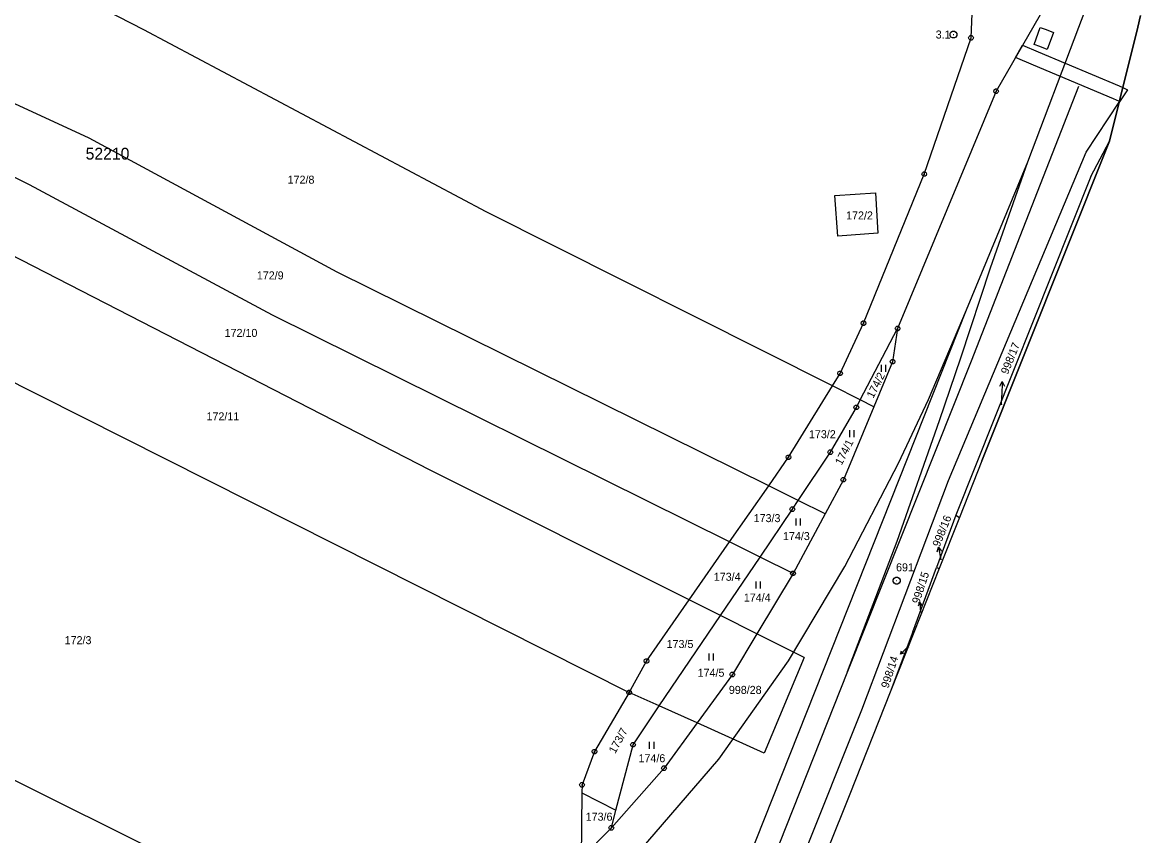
# Model space of a CAD drawing. Extents: x -755359 to -754474, y -1162585 to -1161655.
# Drawn here: x -754987.3 to -754749.7, y -1162144.3 to -1161971.6 of the extents above; entities that cross this region are included whole.
import ezdxf

# ---------------------------------------------------------------- set-up
doc = ezdxf.new("R2010")
doc.units = 0
for name, color, linetype in [('Vrstva 1', 7, 'Continuous'), ('Vrstva 11', 7, 'Continuous'), ('Vrstva 13', 7, 'Continuous'), ('Vrstva 2', 7, 'Continuous'), ('Vrstva 3', 7, 'Continuous'), ('Vrstva 4', 7, 'Continuous'), ('Vrstva 6', 7, 'Continuous'), ('Vrstva 7', 7, 'Continuous'), ('Vrstva 8', 7, 'Continuous')]:
    doc.layers.add(name, color=color, linetype=linetype)

msp = doc.modelspace()

# ---------------------------------------------------------------- linework, layer by layer
at = {"layer": 'Vrstva 1'}
for p, q in [((-754785.77, -1161974.89), (-754784.8, -1161953.94)), ((-754961.49, -1161973.19), (-754992.75, -1161957.04)), ((-754764.95, -1161959.34), (-754780.44, -1161986.21)), ((-754750.32, -1161972.64), (-754749.74, -1161970.12)), ((-754888.73, -1162011.84), (-754961.49, -1161973.19)), ((-754754.27, -1161988.55), (-754750.32, -1161972.64)), ((-754973.07, -1161996.16), (-755018.7, -1161975.2)), ((-754795.69, -1162003.82), (-754785.77, -1161974.89)), ((-754985.77, -1162006.08), (-755029.84, -1161984.47)), ((-754780.44, -1161986.21), (-754801.36, -1162036.63)), ((-754761.32, -1161999.17), (-754754.27, -1161988.55)), ((-754756.33, -1161996.85), (-754754.27, -1161988.55)), ((-754920.4, -1162024.65), (-754973.07, -1161996.16)), ((-754783.47, -1162064.75), (-754756.33, -1161996.85)), ((-754760.29, -1162004.33), (-754756.33, -1161996.85)), ((-754790.52, -1162068.93), (-754761.32, -1161999.17)), ((-754808.6, -1162035.49), (-754795.69, -1162003.82)), ((-754760.29, -1162004.33), (-754789, -1162076.26)), ((-754934.11, -1162033.82), (-754985.77, -1162006.08)), ((-754814.69, -1162008.38), (-754806.06, -1162007.78)), ((-754814.09, -1162016.99), (-754814.69, -1162008.38)), ((-754806.06, -1162007.78), (-754805.56, -1162016.36)), ((-754815.21, -1162048.8), (-754888.73, -1162011.84)), ((-754805.56, -1162016.36), (-754814.09, -1162016.99)), ((-754900.68, -1162066.68), (-754997.44, -1162017.02)), ((-755045.32, -1162019.78), (-754858.37, -1162113.93)), ((-754828.75, -1162070.02), (-754920.4, -1162024.65)), ((-754837.06, -1162081.94), (-754934.11, -1162033.82)), ((-754813.58, -1162046.15), (-754808.6, -1162035.49)), ((-754809.29, -1162051.78), (-754801.36, -1162036.63)), ((-754801.36, -1162036.63), (-754802.42, -1162043.68)), ((-754802.42, -1162043.68), (-754806.4, -1162053.23)), ((-754815.21, -1162048.8), (-754813.58, -1162046.15)), ((-754824.54, -1162063.98), (-754815.21, -1162048.8)), ((-754809.29, -1162051.78), (-754815.21, -1162048.8)), ((-754810.12, -1162053.37), (-754809.29, -1162051.78)), ((-754806.4, -1162053.23), (-754809.29, -1162051.78)), ((-754815.64, -1162062.89), (-754810.12, -1162053.37)), ((-754806.4, -1162053.23), (-754812.88, -1162068.75)), ((-754822.47, -1162073.13), (-754815.64, -1162062.89)), ((-754828.75, -1162070.02), (-754824.54, -1162063.98)), ((-754783.47, -1162064.75), (-754788.22, -1162076.73)), ((-754845.66, -1162094.27), (-754900.68, -1162066.68)), ((-754837.06, -1162081.94), (-754828.75, -1162070.02)), ((-754822.47, -1162073.13), (-754828.75, -1162070.02)), ((-754812.88, -1162068.75), (-754816.76, -1162075.96)), ((-754808.97, -1162117.64), (-754790.52, -1162068.93)), ((-754823.72, -1162075.01), (-754822.47, -1162073.13)), ((-754816.76, -1162075.96), (-754822.47, -1162073.13)), ((-754830.58, -1162085.16), (-754823.72, -1162075.01)), ((-754816.76, -1162075.96), (-754823.58, -1162088.63)), ((-754789, -1162076.26), (-754793.13, -1162087.4)), ((-754788.22, -1162076.73), (-754792.54, -1162087.63)), ((-754789, -1162076.26), (-754788.22, -1162076.73)), ((-754845.66, -1162094.27), (-754837.06, -1162081.94)), ((-754830.58, -1162085.16), (-754837.06, -1162081.94)), ((-754839, -1162097.61), (-754830.58, -1162085.16)), ((-754823.58, -1162088.63), (-754830.58, -1162085.16)), ((-754798.15, -1162101.07), (-754793.13, -1162087.4)), ((-754792.54, -1162087.63), (-754797.91, -1162101.16)), ((-754793.13, -1162087.4), (-754792.54, -1162087.63)), ((-754900.06, -1162176.77), (-755075.64, -1162089.56)), ((-754823.58, -1162088.63), (-754831.28, -1162101.48)), ((-754854.71, -1162107.25), (-754845.66, -1162094.27)), ((-754839, -1162097.61), (-754845.66, -1162094.27)), ((-754851.98, -1162116.8), (-754839, -1162097.61)), ((-754831.28, -1162101.48), (-754839, -1162097.61)), ((-754831.28, -1162101.48), (-754836.46, -1162110.13)), ((-754821.22, -1162106.53), (-754831.28, -1162101.48)), ((-754798.15, -1162101.07), (-754802.96, -1162113.9)), ((-754797.91, -1162101.16), (-754802.96, -1162113.9)), ((-754797.91, -1162101.16), (-754798.15, -1162101.07)), ((-754821.22, -1162106.53), (-754829.74, -1162126.8)), ((-754858.37, -1162113.93), (-754854.71, -1162107.25)), ((-754836.46, -1162110.13), (-754843.96, -1162120.41)), ((-754858.37, -1162113.93), (-754865.75, -1162126.5)), ((-754851.98, -1162116.8), (-754858.37, -1162113.93)), ((-754802.96, -1162113.9), (-754811.54, -1162135.54)), ((-754857.56, -1162125.05), (-754851.98, -1162116.8)), ((-754843.96, -1162120.41), (-754851.98, -1162116.8)), ((-754824.89, -1162157.4), (-754808.97, -1162117.64)), ((-754843.96, -1162120.41), (-754850.97, -1162130.01)), ((-754829.74, -1162126.8), (-754843.96, -1162120.41)), ((-754861.18, -1162138.93), (-754857.56, -1162125.05)), ((-754865.75, -1162126.5), (-754868.4, -1162133.56)), ((-754850.97, -1162130.01), (-754862.16, -1162142.69)), ((-754868.42, -1162135.23), (-754868.56, -1162149.23)), ((-754868.4, -1162133.56), (-754868.42, -1162135.23)), ((-754868.42, -1162135.23), (-754861.18, -1162138.93)), ((-754811.54, -1162135.54), (-754816.22, -1162147.35)), ((-754862.16, -1162142.69), (-754861.18, -1162138.93)), ((-754862.16, -1162142.69), (-754868.56, -1162149.23))]:
    msp.add_line(p, q, dxfattribs=at)
at = {"layer": 'Vrstva 11'}
for p, q in [((-754749.74, -1161970.12), (-754750.32, -1161972.64)), ((-754750.32, -1161972.64), (-754754.27, -1161988.55)), ((-754754.27, -1161988.55), (-754756.33, -1161996.85)), ((-754756.33, -1161996.85), (-754783.47, -1162064.75)), ((-754783.47, -1162064.75), (-754788.22, -1162076.73)), ((-754788.22, -1162076.73), (-754792.54, -1162087.63)), ((-754792.54, -1162087.63), (-754797.91, -1162101.16)), ((-754797.91, -1162101.16), (-754802.96, -1162113.9)), ((-754802.96, -1162113.9), (-754811.54, -1162135.54)), ((-754811.54, -1162135.54), (-754816.22, -1162147.35))]:
    msp.add_line(p, q, dxfattribs=at)
at = {"layer": 'Vrstva 13'}
for p, q in [((-754776.33, -1161979.09), (-754774.82, -1161976.46)), ((-754774.82, -1161976.46), (-754771.51, -1161977.85)), ((-754771.51, -1161977.85), (-754754.32, -1161985.09)), ((-754772.52, -1161980.69), (-754776.33, -1161979.09)), ((-754755.52, -1161987.84), (-754772.52, -1161980.69)), ((-754754.32, -1161985.09), (-754753.5, -1161985.46)), ((-754753.5, -1161985.46), (-754752.53, -1161985.9)), ((-754754.24, -1161988.42), (-754755.52, -1161987.84)), ((-754752.53, -1161985.9), (-754754.2, -1161988.44)), ((-754754.2, -1161988.44), (-754754.24, -1161988.42))]:
    msp.add_line(p, q, dxfattribs=at)
at = {"layer": 'Vrstva 3'}
for p, q in [((-754804.83, -1162044.34), (-754804.83, -1162045.84)), ((-754803.83, -1162045.84), (-754803.83, -1162044.34)), ((-754811.61, -1162058.2), (-754811.61, -1162059.7)), ((-754810.61, -1162059.7), (-754810.61, -1162058.2)), ((-754822.99, -1162076.98), (-754822.99, -1162078.48)), ((-754821.99, -1162078.48), (-754821.99, -1162076.98)), ((-754831.5, -1162090.36), (-754831.5, -1162091.86)), ((-754830.5, -1162091.86), (-754830.5, -1162090.36)), ((-754841.49, -1162105.66), (-754841.49, -1162107.16)), ((-754840.49, -1162107.16), (-754840.49, -1162105.66)), ((-754854.1, -1162124.39), (-754854.1, -1162125.89)), ((-754853.1, -1162125.89), (-754853.1, -1162124.39))]:
    msp.add_line(p, q, dxfattribs=at)
at = {"layer": 'Vrstva 4'}
for p, q in [((-754772.36, -1161976.29), (-754771.05, -1161972.69)), ((-754771.05, -1161972.69), (-754769.84, -1161973.14)), ((-754769.84, -1161973.14), (-754768.22, -1161973.73)), ((-754768.22, -1161973.73), (-754769.56, -1161977.33)), ((-754771.12, -1161976.75), (-754772.36, -1161976.29)), ((-754769.56, -1161977.33), (-754771.12, -1161976.75))]:
    msp.add_line(p, q, dxfattribs=at)
at = {"layer": 'Vrstva 6'}
for p, q in [((-754762.88, -1161972.64), (-754755.18, -1161952.44)), ((-754773.71, -1162001.23), (-754762.88, -1161972.64)), ((-754762.96, -1161985.22), (-754775.37, -1162017.08)), ((-754786.74, -1162032.64), (-754773.71, -1162001.23)), ((-754781.65, -1162023.75), (-754773.71, -1162001.23)), ((-754775.37, -1162017.08), (-754785.74, -1162043.55)), ((-754787.92, -1162042.83), (-754781.65, -1162023.75)), ((-755000.46, -1162571.42), (-754786.74, -1162032.64)), ((-754794.8, -1162051.68), (-754786.74, -1162032.64)), ((-754785.74, -1162043.55), (-754811.99, -1162109.48)), ((-754792.49, -1162056.16), (-754787.92, -1162042.83)), ((-754801.19, -1162065.2), (-754794.8, -1162051.68)), ((-754801.47, -1162081.77), (-754792.49, -1162056.16)), ((-754812.55, -1162087.19), (-754801.19, -1162065.2)), ((-754811.99, -1162109.48), (-754801.47, -1162081.77)), ((-754824.53, -1162107.23), (-754812.55, -1162087.19)), ((-754839.32, -1162128.13), (-754824.53, -1162107.23)), ((-754811.99, -1162109.48), (-754841.46, -1162183.87)), ((-754862.02, -1162154.33), (-754839.32, -1162128.13))]:
    msp.add_line(p, q, dxfattribs=at)
at = {"layer": 'Vrstva 7'}
for p, q in [((-754779.144, -1162047.852), (-754779.25, -1162050.85)), ((-754779.31, -1162052.8), (-754779.25, -1162050.85)), ((-754792.655, -1162083.101), (-754792.19, -1162085.73)), ((-754796.639, -1162094.805), (-754796.49, -1162096.93)), ((-754800.78, -1162105.77), (-754799.31, -1162104.4))]:
    msp.add_line(p, q, dxfattribs=at)
for points in [[(-754779.679, -1162048.834), (-754779.144, -1162047.852), (-754778.68, -1162048.869)], [(-754792.938, -1162084.055), (-754792.655, -1162083.101), (-754792.062, -1162083.9)], [(-754796.943, -1162095.538), (-754796.639, -1162094.805), (-754796.235, -1162095.489)], [(-754800.062, -1162105.559), (-754800.78, -1162105.77), (-754800.519, -1162105.069)]]:
    msp.add_lwpolyline(points, dxfattribs=at)
at = {"layer": 'Vrstva 8'}
for p, q in [((-754789.54, -1161974.17), (-754789.44, -1161974.17)), ((-754785.89, -1161974.89), (-754785.65, -1161974.89)), ((-754780.56, -1161986.21), (-754780.32, -1161986.21)), ((-754795.81, -1162003.82), (-754795.57, -1162003.82)), ((-754808.72, -1162035.49), (-754808.48, -1162035.49)), ((-754801.48, -1162036.63), (-754801.24, -1162036.63)), ((-754802.54, -1162043.68), (-754802.3, -1162043.68)), ((-754813.7, -1162046.15), (-754813.46, -1162046.15)), ((-754810.24, -1162053.37), (-754810, -1162053.37)), ((-754815.76, -1162062.89), (-754815.52, -1162062.89)), ((-754824.66, -1162063.98), (-754824.42, -1162063.98)), ((-754813, -1162068.75), (-754812.76, -1162068.75)), ((-754823.84, -1162075.01), (-754823.6, -1162075.01)), ((-754823.7, -1162088.63), (-754823.46, -1162088.63)), ((-754801.6, -1162090.16), (-754801.5, -1162090.16)), ((-754854.83, -1162107.25), (-754854.59, -1162107.25)), ((-754836.58, -1162110.13), (-754836.34, -1162110.13)), ((-754858.49, -1162113.93), (-754858.25, -1162113.93)), ((-754857.68, -1162125.05), (-754857.44, -1162125.05)), ((-754865.87, -1162126.5), (-754865.63, -1162126.5)), ((-754851.09, -1162130.01), (-754850.85, -1162130.01)), ((-754868.52, -1162133.56), (-754868.28, -1162133.56)), ((-754862.28, -1162142.69), (-754862.04, -1162142.69))]:
    msp.add_line(p, q, dxfattribs=at)
for points in [[(-754789.3, -1161973.45), (-754788.96, -1161973.64), (-754788.77, -1161973.98), (-754788.77, -1161974.37), (-754788.96, -1161974.71), (-754789.3, -1161974.9), (-754789.69, -1161974.9), (-754790.03, -1161974.71), (-754790.22, -1161974.37), (-754790.22, -1161973.98), (-754790.03, -1161973.64), (-754789.69, -1161973.45)], [(-754785.62, -1161974.41), (-754785.37, -1161974.59), (-754785.27, -1161974.88), (-754785.37, -1161975.17), (-754785.62, -1161975.35), (-754785.93, -1161975.35), (-754786.18, -1161975.17), (-754786.28, -1161974.88), (-754786.18, -1161974.59), (-754785.93, -1161974.41)], [(-754780.29, -1161985.73), (-754780.04, -1161985.91), (-754779.94, -1161986.2), (-754780.04, -1161986.49), (-754780.29, -1161986.67), (-754780.6, -1161986.67), (-754780.85, -1161986.49), (-754780.95, -1161986.2), (-754780.85, -1161985.91), (-754780.6, -1161985.73)], [(-754795.54, -1162003.34), (-754795.29, -1162003.52), (-754795.19, -1162003.81), (-754795.29, -1162004.1), (-754795.54, -1162004.28), (-754795.85, -1162004.28), (-754796.1, -1162004.1), (-754796.2, -1162003.81), (-754796.1, -1162003.52), (-754795.85, -1162003.34)], [(-754808.45, -1162035.01), (-754808.2, -1162035.19), (-754808.1, -1162035.48), (-754808.2, -1162035.77), (-754808.45, -1162035.95), (-754808.76, -1162035.95), (-754809.01, -1162035.77), (-754809.11, -1162035.48), (-754809.01, -1162035.19), (-754808.76, -1162035.01)], [(-754801.21, -1162036.15), (-754800.96, -1162036.33), (-754800.86, -1162036.62), (-754800.96, -1162036.91), (-754801.21, -1162037.09), (-754801.52, -1162037.09), (-754801.77, -1162036.91), (-754801.87, -1162036.62), (-754801.77, -1162036.33), (-754801.52, -1162036.15)], [(-754802.27, -1162043.2), (-754802.02, -1162043.38), (-754801.92, -1162043.67), (-754802.02, -1162043.96), (-754802.27, -1162044.14), (-754802.58, -1162044.14), (-754802.83, -1162043.96), (-754802.93, -1162043.67), (-754802.83, -1162043.38), (-754802.58, -1162043.2)], [(-754813.43, -1162045.67), (-754813.18, -1162045.85), (-754813.08, -1162046.14), (-754813.18, -1162046.43), (-754813.43, -1162046.61), (-754813.74, -1162046.61), (-754813.99, -1162046.43), (-754814.09, -1162046.14), (-754813.99, -1162045.85), (-754813.74, -1162045.67)], [(-754809.97, -1162052.89), (-754809.72, -1162053.07), (-754809.62, -1162053.36), (-754809.72, -1162053.65), (-754809.97, -1162053.83), (-754810.28, -1162053.83), (-754810.53, -1162053.65), (-754810.63, -1162053.36), (-754810.53, -1162053.07), (-754810.28, -1162052.89)], [(-754824.39, -1162063.5), (-754824.14, -1162063.68), (-754824.04, -1162063.97), (-754824.14, -1162064.26), (-754824.39, -1162064.44), (-754824.7, -1162064.44), (-754824.95, -1162064.26), (-754825.05, -1162063.97), (-754824.95, -1162063.68), (-754824.7, -1162063.5)], [(-754815.49, -1162062.41), (-754815.24, -1162062.59), (-754815.14, -1162062.88), (-754815.24, -1162063.17), (-754815.49, -1162063.35), (-754815.8, -1162063.35), (-754816.05, -1162063.17), (-754816.15, -1162062.88), (-754816.05, -1162062.59), (-754815.8, -1162062.41)], [(-754812.73, -1162068.27), (-754812.48, -1162068.45), (-754812.38, -1162068.74), (-754812.48, -1162069.03), (-754812.73, -1162069.21), (-754813.04, -1162069.21), (-754813.29, -1162069.03), (-754813.39, -1162068.74), (-754813.29, -1162068.45), (-754813.04, -1162068.27)], [(-754823.57, -1162074.53), (-754823.32, -1162074.71), (-754823.22, -1162075), (-754823.32, -1162075.29), (-754823.57, -1162075.47), (-754823.88, -1162075.47), (-754824.13, -1162075.29), (-754824.23, -1162075), (-754824.13, -1162074.71), (-754823.88, -1162074.53)], [(-754823.43, -1162088.15), (-754823.18, -1162088.33), (-754823.08, -1162088.62), (-754823.18, -1162088.91), (-754823.43, -1162089.09), (-754823.74, -1162089.09), (-754823.99, -1162088.91), (-754824.09, -1162088.62), (-754823.99, -1162088.33), (-754823.74, -1162088.15)], [(-754801.36, -1162089.44), (-754801.02, -1162089.63), (-754800.83, -1162089.97), (-754800.83, -1162090.36), (-754801.02, -1162090.7), (-754801.36, -1162090.89), (-754801.75, -1162090.89), (-754802.09, -1162090.7), (-754802.28, -1162090.36), (-754802.28, -1162089.97), (-754802.09, -1162089.63), (-754801.75, -1162089.44)], [(-754854.56, -1162106.77), (-754854.31, -1162106.95), (-754854.21, -1162107.24), (-754854.31, -1162107.53), (-754854.56, -1162107.71), (-754854.87, -1162107.71), (-754855.12, -1162107.53), (-754855.22, -1162107.24), (-754855.12, -1162106.95), (-754854.87, -1162106.77)], [(-754836.31, -1162109.65), (-754836.06, -1162109.83), (-754835.96, -1162110.12), (-754836.06, -1162110.41), (-754836.31, -1162110.59), (-754836.62, -1162110.59), (-754836.87, -1162110.41), (-754836.97, -1162110.12), (-754836.87, -1162109.83), (-754836.62, -1162109.65)], [(-754858.22, -1162113.45), (-754857.97, -1162113.63), (-754857.87, -1162113.92), (-754857.97, -1162114.21), (-754858.22, -1162114.39), (-754858.53, -1162114.39), (-754858.78, -1162114.21), (-754858.88, -1162113.92), (-754858.78, -1162113.63), (-754858.53, -1162113.45)], [(-754857.41, -1162124.57), (-754857.16, -1162124.75), (-754857.06, -1162125.04), (-754857.16, -1162125.33), (-754857.41, -1162125.51), (-754857.72, -1162125.51), (-754857.97, -1162125.33), (-754858.07, -1162125.04), (-754857.97, -1162124.75), (-754857.72, -1162124.57)], [(-754865.6, -1162126.02), (-754865.35, -1162126.2), (-754865.25, -1162126.49), (-754865.35, -1162126.78), (-754865.6, -1162126.96), (-754865.91, -1162126.96), (-754866.16, -1162126.78), (-754866.26, -1162126.49), (-754866.16, -1162126.2), (-754865.91, -1162126.02)], [(-754850.82, -1162129.53), (-754850.57, -1162129.71), (-754850.47, -1162130), (-754850.57, -1162130.29), (-754850.82, -1162130.47), (-754851.13, -1162130.47), (-754851.38, -1162130.29), (-754851.48, -1162130), (-754851.38, -1162129.71), (-754851.13, -1162129.53)], [(-754868.25, -1162133.08), (-754868, -1162133.26), (-754867.9, -1162133.55), (-754868, -1162133.84), (-754868.25, -1162134.02), (-754868.56, -1162134.02), (-754868.81, -1162133.84), (-754868.91, -1162133.55), (-754868.81, -1162133.26), (-754868.56, -1162133.08)], [(-754862.01, -1162142.21), (-754861.76, -1162142.39), (-754861.66, -1162142.68), (-754861.76, -1162142.97), (-754862.01, -1162143.15), (-754862.32, -1162143.15), (-754862.57, -1162142.97), (-754862.67, -1162142.68), (-754862.57, -1162142.39), (-754862.32, -1162142.21)]]:
    msp.add_lwpolyline(points, close=True, dxfattribs=at)

# ---------------------------------------------------------------- texts
at = {"layer": 'Vrstva 11'}
msp.add_text('52210', height=2.5, dxfattribs=at).set_placement((-754973.837, -1162000.73))
at = {"layer": 'Vrstva 2'}
for s, height, p in [('172/8', 1.7, (-754930.927, -1162005.86)), ('172/2', 1.7, (-754812.297, -1162013.45)), ('172/9', 1.7, (-754937.467, -1162026.19)), ('172/10', 1.7, (-754944.307, -1162038.41)), ('172/11', 1.7, (-754948.157, -1162056.13)), ('998/17', 0.1, (-754779.296, -1162052.8)), ('173/2', 1.7, (-754820.187, -1162059.92)), ('173/3', 1.7, (-754831.937, -1162077.75)), ('174/3', 1.7, (-754825.707, -1162081.56)), ('998/16', 0.1, (-754792.176, -1162085.73)), ('173/4', 1.7, (-754840.407, -1162090.2)), ('174/4', 1.7, (-754834.027, -1162094.62)), ('998/15', 0.1, (-754796.476, -1162096.93)), ('172/3', 1.7, (-754978.287, -1162103.67)), ('173/5', 1.7, (-754850.427, -1162104.49)), ('998/14', 0.1, (-754799.296, -1162104.4)), ('174/5', 1.7, (-754843.837, -1162110.59)), ('998/28', 1.7, (-754837.203, -1162114.23)), ('174/6', 1.7, (-754856.397, -1162128.75)), ('173/6', 1.7, (-754867.617, -1162141.17))]:
    msp.add_text(s, height=height, dxfattribs=at).set_placement(p)
for s, rotation, p in [('174/2', 63.02536, (-754806.542, -1162051.58)), ('174/1', 63.02536, (-754813.252, -1162065.79)), ('173/7', 61.19189, (-754861.351, -1162127.056))]:
    msp.add_text(s, height=1.7, rotation=rotation, dxfattribs=at).set_placement(p)
at = {"layer": 'Vrstva 7'}
for s, rotation, p in [('998/17', 68.01009, (-754777.941, -1162046.49)), ('998/16', 68.01009, (-754792.476, -1162083.17)), ('998/15', 72.02079, (-754796.769, -1162095.237)), ('998/14', 72.02079, (-754803.333, -1162113.172))]:
    msp.add_text(s, height=1.7, rotation=rotation, dxfattribs=at).set_placement(p)
at = {"layer": 'Vrstva 8'}
for s, p in [('3.1', (-754793.271, -1161975.02)), ('691', (-754801.693, -1162088.2))]:
    msp.add_text(s, height=1.7, dxfattribs=at).set_placement(p)

doc.saveas('drawing.dxf')
